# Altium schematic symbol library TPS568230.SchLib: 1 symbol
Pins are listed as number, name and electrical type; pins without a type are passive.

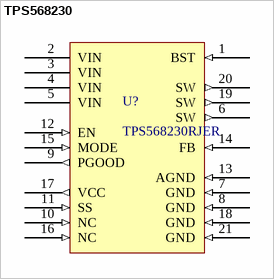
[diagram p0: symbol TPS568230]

## TPS568230
designator U?, comment TPS568230RJER
footprint RJE0020A (PQFN, 20-Leads, Body 3.00x3.00mm, Pitch 0.45mm, Thermal Pad 0.76x0.68mm, IPC Medium Density)
pins: 1 BST (in), 2 VIN (power), 3 VIN (power), 4 VIN (power), 5 VIN (power), 6 SW (out), 7 GND (in), 8 GND (in), 9 PGOOD (out), 10 NC (in), 11 SS (in), 12 EN (in), 13 AGND (in), 14 FB (in), 15 MODE (in), 16 NC (in), 17 VCC (out), 18 GND (in), 19 SW (out), 20 SW (out), 21 GND (in)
